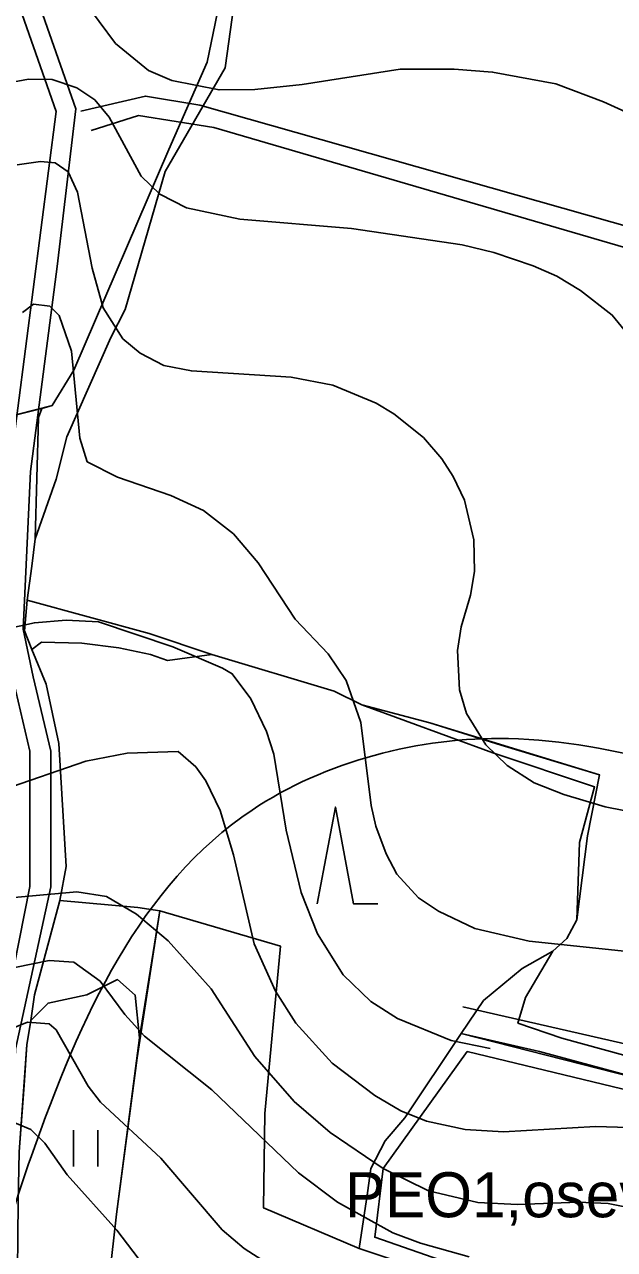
# Model space of a CAD drawing. Extents: x -684583 to -680383, y -1157874 to -1154904.
# Drawn here: x -683237.5 to -683067.1, y -1156658.6 to -1156304.8 of the extents above; entities that cross this region are included whole.
import ezdxf

# ---------------------------------------------------------------- set-up
doc = ezdxf.new("R2010")
doc.units = 0
for name, color, linetype in [('01_OBVOD PÚ', 7, 'Continuous'), ('01_VRSTEVNICE', 7, 'Continuous'), ('02_KULTURY STAV', 7, 'Continuous'), ('03_PC_NÁVRH', 7, 'Continuous'), ('03_PC_OBJEKTY_NÁVRH', 7, 'Continuous'), ('03_PC_STAV', 7, 'Continuous'), ('04_ZPF_OP_ORGAN', 7, 'Continuous'), ('06_BIOGEOGRAFIE', 7, 'Continuous'), ('06_ÚSES_IP', 7, 'Continuous')]:
    doc.layers.add(name, color=color, linetype=linetype)

msp = doc.modelspace()

# ---------------------------------------------------------------- linework, layer by layer
at = {"layer": '01_OBVOD PÚ'}
for points in [[(-683217.31, -1156704.71), (-683210.97, -1156648.47), (-683205, -1156603.23), (-683198.42, -1156560.83), (-683163.62, -1156570.98), (-683168.11, -1156619.33), (-683168.47, -1156646.61), (-683140.88, -1156658.35), (-683073.72, -1156680.66)], [(-683073.72, -1156680.66), (-683140.88, -1156658.35), (-683168.47, -1156646.61), (-683168.11, -1156619.33), (-683163.62, -1156570.98), (-683198.42, -1156560.83), (-683204.31, -1156597.48), (-683205, -1156603.23), (-683210.97, -1156648.47), (-683217.31, -1156704.71)]]:
    msp.add_lwpolyline(points, dxfattribs=at)
at = {"layer": '01_VRSTEVNICE'}
for points in [[(-683029.24, -1156345.81), (-683070.32, -1156327.12), (-683084.01, -1156321.99), (-683102.31, -1156318.54), (-683113.42, -1156317.72), (-683129.05, -1156317.72), (-683157.33, -1156322.13), (-683171.02, -1156323.56), (-683181.29, -1156323.7), (-683194.99, -1156320.99), (-683201.69, -1156318.14), (-683211.25, -1156310.29), (-683220.66, -1156297.46)], [(-683063.47, -1156394.03), (-683067.75, -1156388.75), (-683076.88, -1156381.61), (-683083.73, -1156377.48), (-683090.57, -1156374.48), (-683101.98, -1156370.63), (-683111.11, -1156368.49), (-683143.07, -1156363.78), (-683175.3, -1156361.07), (-683190.71, -1156357.79), (-683198.41, -1156353.8), (-683203.83, -1156348.66), (-683213.1, -1156331.55), (-683217.24, -1156326.55), (-683222.38, -1156323.13), (-683229.51, -1156320.71), (-683236.35, -1156320.56), (-683242.06, -1156321.7)], [(-683052.63, -1156534.1), (-683069.75, -1156530.82), (-683081.73, -1156527.25), (-683090.29, -1156523.83), (-683098.13, -1156518.84), (-683104.27, -1156512.85), (-683109.83, -1156503.86), (-683111.83, -1156497.01), (-683112.4, -1156485.6), (-683111.4, -1156478.76), (-683108.69, -1156469.63), (-683107.55, -1156462.78), (-683107.69, -1156453.65), (-683110.4, -1156442.24), (-683113.68, -1156435.39), (-683116.96, -1156430.26), (-683122.24, -1156424.12), (-683130.8, -1156417.28), (-683135.93, -1156414.14), (-683148.49, -1156409), (-683160.47, -1156406.72), (-683189.28, -1156404.87), (-683197.27, -1156403.3), (-683204.12, -1156399.73), (-683209.11, -1156395.59), (-683214.82, -1156386.61), (-683217.95, -1156375.2), (-683222.23, -1156353.23), (-683224.94, -1156347.38), (-683228.65, -1156344.81), (-683232.93, -1156344.38), (-683239.64, -1156345.38)], [(-683238.07, -1156388.03), (-683234.93, -1156385.61), (-683230.22, -1156386.18), (-683227.51, -1156388.89), (-683223.95, -1156399.16), (-683221.52, -1156424.26), (-683219.38, -1156431.11), (-683210.68, -1156435.53), (-683195.27, -1156440.81), (-683185.86, -1156445.23), (-683177.16, -1156451.94), (-683170.03, -1156460.35), (-683159.33, -1156476.62), (-683149.77, -1156486.6), (-683144.63, -1156494.3), (-683140.36, -1156506.43), (-683137.36, -1156530.39), (-683136.08, -1156536.38), (-683133.08, -1156544.37), (-683129.94, -1156550.22), (-683123.67, -1156557.07), (-683117.96, -1156560.92), (-683107.41, -1156565.91), (-683091.71, -1156569.62), (-683056.05, -1156573.33)], [(-683102.98, -1156600.57), (-683114.25, -1156598.29), (-683129.8, -1156591.87), (-683137.5, -1156587.02), (-683145.49, -1156579.32), (-683152.91, -1156567.48), (-683157.62, -1156555.5), (-683161.9, -1156537.53), (-683165.46, -1156515.56), (-683167.6, -1156509), (-683172.17, -1156499.58), (-683177.53, -1156492.32), (-683180.3, -1156490.74), (-683194.7, -1156484.6), (-683216.1, -1156477.33), (-683225.51, -1156476.9), (-683234.64, -1156477.61), (-683252.9, -1156481.61)], [(-683056.62, -1156623.54), (-683072.6, -1156623.11), (-683099.13, -1156624.68), (-683110.26, -1156623.97), (-683121.38, -1156621.54), (-683128.8, -1156618.55), (-683136.36, -1156614.12), (-683148.63, -1156604.85), (-683159.18, -1156593.3), (-683165.03, -1156584.03), (-683171.17, -1156570.33), (-683177.16, -1156544.66), (-683181.01, -1156531.82), (-683185.15, -1156523.26), (-683188, -1156519.27), (-683193.13, -1156514.84), (-683207.83, -1156515.27), (-683219.81, -1156517.55), (-683243.77, -1156525.83)], [(-683265.17, -1156559.21), (-683222.38, -1156555.35), (-683213.82, -1156556.64), (-683205.12, -1156561.77), (-683195.99, -1156569.48), (-683183.58, -1156583.31), (-683171.02, -1156602.86), (-683159.61, -1156615.84), (-683149.2, -1156624.82), (-683133.94, -1156635.23), (-683120.81, -1156641.65), (-683106.55, -1156645.08), (-683095.14, -1156645.65), (-683077.45, -1156644.93), (-683068.89, -1156645.36), (-683038.08, -1156651.5)], [(-683240.35, -1156577.18), (-683230.36, -1156575.18), (-683223.23, -1156575.61), (-683215.67, -1156581.17), (-683208.54, -1156590.73), (-683202.83, -1156597.01), (-683183.43, -1156612.55), (-683158.33, -1156636.52), (-683147.06, -1156644.93), (-683131.08, -1156653.78), (-683123.1, -1156656.78), (-683109.12, -1156660.77)], [(-683382.14, -1156668.33), (-683373.29, -1156658.2), (-683364.16, -1156645.93), (-683353.61, -1156636.38), (-683347.9, -1156632.1), (-683329.93, -1156623.25), (-683314.52, -1156613.27), (-683306.54, -1156610.13), (-683298.55, -1156607.99), (-683274.58, -1156605.14), (-683264.6, -1156602), (-683252.62, -1156599.43), (-683236.64, -1156593.01), (-683230.36, -1156593.44), (-683228.37, -1156595.15), (-683219.09, -1156611.41), (-683215.53, -1156616.12), (-683198.13, -1156632.24), (-683180.44, -1156652.92), (-683174.02, -1156658.34), (-683167.6, -1156662.48)], [(-683338.35, -1156661.34), (-683330.07, -1156653.92), (-683316.52, -1156645.22), (-683305.68, -1156637.38), (-683299.69, -1156633.95), (-683287.71, -1156630.1), (-683265.74, -1156627.1), (-683243.77, -1156621.97), (-683239.78, -1156622.25), (-683235.64, -1156623.97), (-683231.65, -1156627.96), (-683225.23, -1156637.09), (-683210.82, -1156653.07), (-683195.13, -1156673.61)]]:
    msp.add_lwpolyline(points, dxfattribs=at)
at = {"layer": '02_KULTURY STAV'}
for points in [[(-683171.14, -1156249.94), (-683184.73, -1156315.73), (-683195.8, -1156340.96), (-683223.29, -1156404.62), (-683229.5, -1156414.89), (-683248.89, -1156419.76), (-683269.76, -1156388.87), (-683281.59, -1156384.74), (-683304.9, -1156383.71), (-683338.64, -1156382.37), (-683349.03, -1156390.61), (-683358.7, -1156410.42), (-683379.76, -1156446.48), (-683381.62, -1156451.71), (-683380.17, -1156471.46), (-683371.92, -1156481.45), (-683379.32, -1156505.79), (-683389.29, -1156507.28), (-683397.99, -1156506.51), (-683420.76, -1156503.71), (-683434.86, -1156514.91), (-683443.57, -1156532.32), (-683471.62, -1156560.57)], [(-683176.55, -1156295.75), (-683179.6, -1156317.32), (-683196.9, -1156347.32), (-683208.45, -1156387.1), (-683212.55, -1156395.18), (-683225.29, -1156423.89), (-683228.37, -1156436.14), (-683234.45, -1156453.38), (-683233.49, -1156418.32), (-683232.53, -1156415.71), (-683229.5, -1156414.89), (-683223.29, -1156404.62), (-683195.8, -1156340.96), (-683184.73, -1156315.73), (-683171.14, -1156249.94)], [(-683033.47, -1156611), (-683082.29, -1156597.58), (-683095.01, -1156593.22), (-683092.79, -1156585.88), (-683084.93, -1156572.48), (-683080.84, -1156568.8), (-683077.97, -1156563.38), (-683074.85, -1156539.12), (-683071.42, -1156521.58), (-683120.39, -1156506.54), (-683140.1, -1156501.34), (-683148.04, -1156497.37), (-683183.45, -1156486.8), (-683201.52, -1156480.71), (-683236.75, -1156471.12), (-683235.38, -1156461.31), (-683234.45, -1156453.38), (-683228.37, -1156436.14), (-683225.29, -1156423.89), (-683212.55, -1156395.18), (-683208.45, -1156387.1), (-683196.9, -1156347.32), (-683179.6, -1156317.32), (-683176.55, -1156295.75)], [(-683248.89, -1156419.76), (-683232.53, -1156415.71), (-683233.49, -1156418.32), (-683234.45, -1156453.38), (-683235.38, -1156461.31), (-683236.75, -1156471.12), (-683237.51, -1156479.9), (-683235.37, -1156485.35), (-683231.28, -1156495.3), (-683227.6, -1156512.52), (-683225.49, -1156548.01), (-683227.28, -1156557.83), (-683234.61, -1156585.04), (-683235.71, -1156592.49), (-683236.8, -1156599.48), (-683239.01, -1156630.41)], [(-683152.95, -1156558.84), (-683147.7, -1156530.84), (-683142.45, -1156558.84), (-683135.45, -1156558.84)], [(-683217.31, -1156704.71), (-683210.97, -1156648.47), (-683205, -1156603.23), (-683198.42, -1156560.83), (-683163.62, -1156570.98), (-683168.11, -1156619.33), (-683168.47, -1156646.61), (-683140.88, -1156658.35), (-683073.72, -1156680.66)], [(-683223.35, -1156624.19), (-683223.35, -1156634.69)], [(-683216.35, -1156624.19), (-683216.35, -1156634.69)]]:
    msp.add_lwpolyline(points, dxfattribs=at)
for points in [[(-683183.45, -1156486.8), (-683196.25, -1156488.53), (-683201.11, -1156486.74), (-683210.27, -1156484.89), (-683220.91, -1156483.53), (-683232.6, -1156483.18), (-683235.37, -1156485.35), (-683237.51, -1156479.9), (-683236.75, -1156471.12), (-683201.52, -1156480.71)], [(-683231.28, -1156495.3), (-683235.37, -1156485.35), (-683232.6, -1156483.18), (-683220.91, -1156483.53), (-683210.27, -1156484.89), (-683201.11, -1156486.74), (-683196.25, -1156488.53), (-683183.45, -1156486.8), (-683148.04, -1156497.37), (-683140.1, -1156501.34), (-683102.26, -1156515.14), (-683072.87, -1156525.04), (-683077.2, -1156541.11), (-683077.2, -1156541.11), (-683077.97, -1156563.38), (-683080.84, -1156568.8), (-683084.93, -1156572.48), (-683093.79, -1156577.44), (-683104.92, -1156586.73), (-683111.36, -1156596.26), (-683127.66, -1156620.6), (-683133.3, -1156627.22), (-683137.49, -1156635.26), (-683138.49, -1156642.27), (-683140.88, -1156658.35), (-683168.47, -1156646.61), (-683168.11, -1156619.33), (-683163.62, -1156570.98), (-683198.42, -1156560.83), (-683204.81, -1156559.82), (-683227.28, -1156557.83), (-683225.49, -1156548.01), (-683227.6, -1156512.52)], [(-683099.84, -1156513), (-683071.42, -1156521.58), (-683074.85, -1156539.12), (-683077.97, -1156563.38), (-683077.2, -1156541.11), (-683072.87, -1156525.04), (-683102.26, -1156515.14), (-683140.1, -1156501.34), (-683120.39, -1156506.54)], [(-683227.28, -1156557.83), (-683204.81, -1156559.82), (-683198.42, -1156560.83), (-683204.31, -1156597.48), (-683205.51, -1156585.15), (-683210.65, -1156580.69), (-683219.53, -1156585.09), (-683230.72, -1156587.44), (-683235.71, -1156592.49), (-683234.61, -1156585.04)], [(-683092.79, -1156585.88), (-683084.93, -1156572.48), (-683093.79, -1156577.44), (-683104.92, -1156586.73), (-683111.36, -1156596.26), (-683088.76, -1156601.48), (-683052.03, -1156611.32), (-683020.92, -1156619.13), (-682998.1, -1156623.73), (-682980.21, -1156628.28), (-682966.28, -1156635.31), (-682962.69, -1156639.04), (-682954.15, -1156604.14), (-682961.33, -1156617), (-682968.71, -1156622.54), (-682980.17, -1156623.7), (-682990.2, -1156620.86), (-683033.47, -1156611), (-683082.29, -1156597.58), (-683095.01, -1156593.22)], [(-683239.6, -1156674.58), (-683235.72, -1156673.83), (-683230.34, -1156675.52), (-683226.22, -1156679.98), (-683225.59, -1156686.55), (-683222.89, -1156686.61), (-683224.21, -1156716.74), (-683226.06, -1156725.48), (-683217.31, -1156704.71), (-683210.97, -1156648.47), (-683204.31, -1156597.48), (-683205.51, -1156585.15), (-683210.65, -1156580.69), (-683219.53, -1156585.09), (-683230.72, -1156587.44), (-683235.71, -1156592.49), (-683236.8, -1156599.48), (-683237.66, -1156611.13), (-683239.01, -1156630.41), (-683239.35, -1156645)], [(-683111.36, -1156596.26), (-683052.03, -1156611.32), (-683020.92, -1156619.13), (-682998.1, -1156623.73), (-682980.21, -1156628.28), (-682966.28, -1156635.31), (-682962.69, -1156639.04), (-682976.5, -1156701.12), (-683073.72, -1156680.66), (-683140.88, -1156658.35), (-683138.49, -1156642.27), (-683137.49, -1156635.26), (-683133.3, -1156627.22), (-683127.66, -1156620.6)]]:
    msp.add_lwpolyline(points, close=True, dxfattribs=at)
at = {"layer": '03_PC_NÁVRH'}
msp.add_lwpolyline([(-682898.58, -1156410.84), (-683039.99, -1156369.8), (-683186.84, -1156328.1), (-683202.59, -1156325.5), (-683221.21, -1156329.82)], dxfattribs=at)
at = {"layer": '03_PC_OBJEKTY_NÁVRH'}
for points in [[(-683174.65, -1155937.35), (-683210.22, -1156053.67), (-683213.15, -1156063.25), (-683222.33, -1156079.87), (-683239.53, -1156106.26), (-683245.78, -1156132.85), (-683252.62, -1156185.25), (-683250.28, -1156264.23), (-683244.8, -1156283.2), (-683228.39, -1156329.92), (-683241.68, -1156432.76), (-683244.02, -1156480.07), (-683236.01, -1156514.67), (-683236.01, -1156553.77), (-683245.39, -1156601.08), (-683248.71, -1156657), (-683254.96, -1156720.15), (-683258.68, -1156736.37), (-683280.56, -1156777.62), (-683294.63, -1156809.69), (-683298.73, -1156825.13), (-683296.59, -1156836.67)], [(-682908.91, -1156414.57), (-683182.86, -1156334.61), (-683204.55, -1156331.09), (-683218.23, -1156335.4)]]:
    msp.add_lwpolyline(points, dxfattribs=at)
at = {"layer": '03_PC_STAV'}
msp.add_lwpolyline([(-683239.83, -1156280.24), (-683222.66, -1156329.19), (-683228.08, -1156374.72), (-683235.8, -1156433.94), (-683237.9, -1156479.43), (-683235.03, -1156493.24), (-683229.88, -1156514.73), (-683229.88, -1156553.84), (-683240.11, -1156600.78), (-683242.65, -1156661.68), (-683249.53, -1156720.73), (-683253.54, -1156738.98), (-683290.99, -1156812.56), (-683293.44, -1156824.43), (-683291.03, -1156839.88), (-683283.21, -1156847.9)], dxfattribs=at)
at = {"layer": '04_ZPF_OP_ORGAN'}
msp.add_lwpolyline([(-683109.63, -1156601.48), (-682983.62, -1156631.85), (-682967.02, -1156641.18), (-682979.45, -1156695.86), (-683071.68, -1156677.56), (-683136.35, -1156655.1), (-683133.94, -1156635.23)], close=True, dxfattribs=at)
at = {"layer": '06_BIOGEOGRAFIE'}
for points in [[(-682624.87, -1154935.44), (-682669.05, -1155140.04), (-682739.65, -1155253.72), (-682834.36, -1155382.91), (-682941.12, -1155661.96), (-683008.28, -1155760.14), (-683056.49, -1155810.09), (-683084.04, -1155808.37), (-683154.45, -1155886.49), (-683231.94, -1156062.19), (-683280.08, -1156211.64), (-683362.74, -1156430.39), (-683497.05, -1156731.83), (-683541.82, -1156781.78), (-683638.25, -1156792.12), (-683701.96, -1156768), (-683817.33, -1156693.94)], [(-683099.47, -1156889.99), (-683108.08, -1156852.09), (-683133.91, -1156841.76), (-683133.91, -1156814.2), (-683132.19, -1156784.91), (-683147.69, -1156747.02), (-683189.01, -1156748.74), (-683242.39, -1156712.57), (-683235.51, -1156631.61), (-683171.79, -1156531.71), (-683097.75, -1156511.04), (-683004.76, -1156526.54), (-682887.67, -1156483.48), (-682868.73, -1156459.36), (-682823.96, -1156452.47), (-682839.46, -1156516.2), (-682863.56, -1156605.77), (-682887.67, -1156736.68), (-682923.83, -1156891.71), (-682934.16, -1156915.82), (-682965.16, -1156929.6), (-683004.76, -1156926.16)]]:
    msp.add_spline(points, degree=3, dxfattribs=at)
at = {"layer": '06_ÚSES_IP'}
msp.add_lwpolyline([(-683110.87, -1156588.52), (-682978.56, -1156618.79)], dxfattribs=at)

# ---------------------------------------------------------------- texts
at = {"layer": '04_ZPF_OP_ORGAN'}
msp.add_text('PEO1,osev.postup', height=13, dxfattribs=at).set_placement((-683144.96, -1156649.32))

doc.saveas('drawing.dxf')
